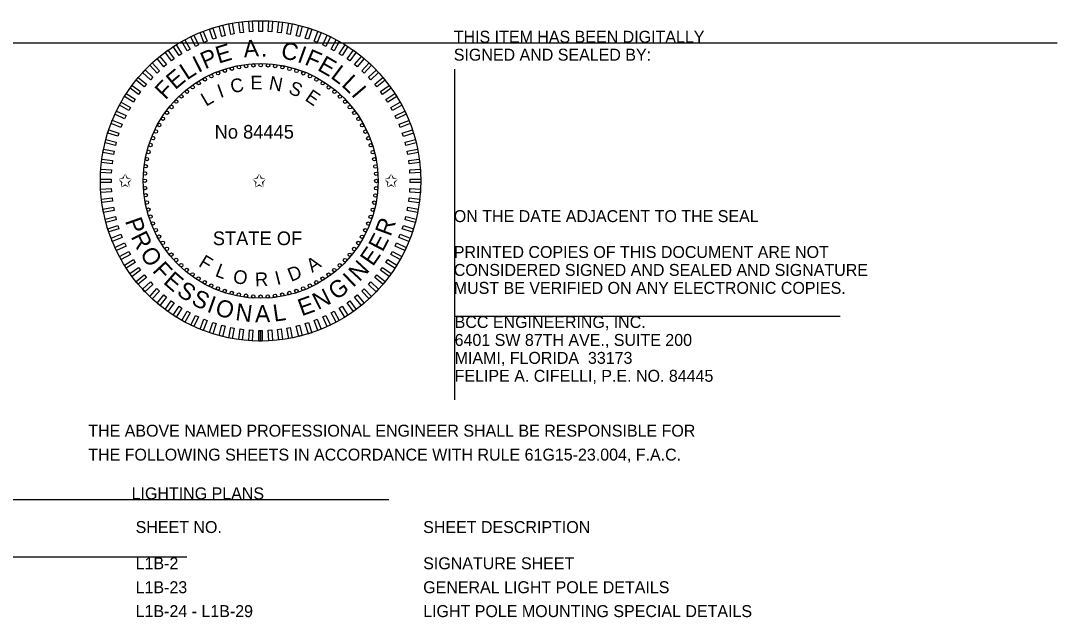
# Model space of a CAD drawing. Extents: x -811.2 to -755.6, y -2295.2 to -2235.1.
# Drawn here: x -802.94 to -796.87, y -2238.99 to -2235.5 of the extents above; entities that cross this region are included whole.
import ezdxf

# ---------------------------------------------------------------- set-up
doc = ezdxf.new("R2010")
doc.units = 0
for name, color, linetype in [('Logo_dp', 7, 'Continuous'), ('NonPlottingEle_dp', 7, 'Continuous'), ('ScratchEle_dp', 7, 'Continuous'), ('TextMisc', 7, 'Continuous'), ('TextNotes', 7, 'Continuous')]:
    doc.layers.add(name, color=color, linetype=linetype)

msp = doc.modelspace()

# ---------------------------------------------------------------- linework, layer by layer
at = {"layer": 'Logo_dp'}
for p, q in [((-801.5429, -2237.3754), (-801.5431, -2237.3129)), ((-801.5329, -2237.3754), (-801.5331, -2237.3129)), ((-801.5229, -2237.3754), (-801.5231, -2237.3129))]:
    msp.add_line(p, q, dxfattribs=at)
for points in [[(-801.6869, -2235.5764), (-801.7067, -2235.5802), (-801.7184, -2235.5189), (-801.6986, -2235.5151)], [(-801.6325, -2235.5685), (-801.6525, -2235.571), (-801.6603, -2235.5091), (-801.6403, -2235.5065)], [(-801.5777, -2235.5639), (-801.5978, -2235.5652), (-801.6018, -2235.5029), (-801.5816, -2235.5016)], [(-801.5227, -2235.5629), (-801.5429, -2235.5629), (-801.5429, -2235.5004), (-801.5227, -2235.5004)], [(-801.4678, -2235.5652), (-801.488, -2235.564), (-801.484, -2235.5016), (-801.4639, -2235.5029)], [(-801.4131, -2235.571), (-801.4332, -2235.5685), (-801.4254, -2235.5066), (-801.4053, -2235.5091)], [(-801.359, -2235.5803), (-801.3788, -2235.5765), (-801.3671, -2235.5152), (-801.3473, -2235.5189)], [(-801.8456, -2235.6206), (-801.8643, -2235.628), (-801.8873, -2235.5699), (-801.8686, -2235.5625)], [(-801.7936, -2235.6025), (-801.8128, -2235.6088), (-801.8321, -2235.5494), (-801.8129, -2235.5432)], [(-801.7407, -2235.5878), (-801.7602, -2235.5928), (-801.7758, -2235.5324), (-801.7562, -2235.5273)], [(-801.3054, -2235.5929), (-801.325, -2235.5879), (-801.3095, -2235.5274), (-801.2899, -2235.5324)], [(-801.2528, -2235.6088), (-801.272, -2235.6026), (-801.2527, -2235.5432), (-801.2335, -2235.5494)], [(-801.2013, -2235.6281), (-801.2201, -2235.6206), (-801.1971, -2235.5626), (-801.1783, -2235.57)], [(-801.9455, -2235.6662), (-801.9632, -2235.6759), (-801.9933, -2235.6212), (-801.9756, -2235.6115)], [(-801.8963, -2235.6418), (-801.9145, -2235.6504), (-801.9411, -2235.5939), (-801.9229, -2235.5853)], [(-801.1511, -2235.6505), (-801.1694, -2235.6419), (-801.1428, -2235.5854), (-801.1246, -2235.594)], [(-801.1025, -2235.676), (-801.1201, -2235.6663), (-801.0901, -2235.6116), (-801.0724, -2235.6213)], [(-802.039, -2235.724), (-802.0553, -2235.7359), (-802.092, -2235.6853), (-802.0757, -2235.6735)], [(-801.9932, -2235.6936), (-802.0102, -2235.7044), (-802.0437, -2235.6517), (-802.0266, -2235.6409)], [(-801.0555, -2235.7045), (-801.0725, -2235.6937), (-801.039, -2235.641), (-801.022, -2235.6518)], [(-801.0104, -2235.736), (-801.0267, -2235.7241), (-800.99, -2235.6736), (-800.9737, -2235.6854)], [(-802.1245, -2235.793), (-802.1392, -2235.8069), (-802.182, -2235.7613), (-802.1672, -2235.7475)], [(-802.0828, -2235.7572), (-802.0984, -2235.77), (-802.1382, -2235.7219), (-802.1226, -2235.7091)], [(-800.9673, -2235.7702), (-800.9829, -2235.7573), (-800.9431, -2235.7092), (-800.9275, -2235.722)], [(-800.9265, -2235.807), (-800.9412, -2235.7932), (-800.8985, -2235.7477), (-800.8838, -2235.7615)], [(-802.1638, -2235.8315), (-802.1776, -2235.8462), (-802.2232, -2235.8034), (-802.2093, -2235.7887)], [(-800.8881, -2235.8463), (-800.9019, -2235.8316), (-800.8564, -2235.7889), (-800.8426, -2235.8036)], [(-802.2349, -2235.9153), (-802.2467, -2235.9316), (-802.2972, -2235.8949), (-802.2854, -2235.8786)], [(-802.2007, -2235.8723), (-802.2135, -2235.8878), (-802.2616, -2235.848), (-802.2488, -2235.8325)], [(-800.8522, -2235.888), (-800.8651, -2235.8724), (-800.817, -2235.8326), (-800.8041, -2235.8482)], [(-800.819, -2235.9318), (-800.8309, -2235.9155), (-800.7804, -2235.8788), (-800.7685, -2235.8951)], [(-802.2663, -2235.9604), (-802.2771, -2235.9775), (-802.3298, -2235.944), (-802.319, -2235.927)], [(-800.7887, -2235.9776), (-800.7995, -2235.9606), (-800.7468, -2235.9271), (-800.7359, -2235.9442)], [(-802.2948, -2236.0074), (-802.3045, -2236.0251), (-802.3593, -2235.995), (-802.3495, -2235.9773)], [(-800.7612, -2236.0253), (-800.7709, -2236.0076), (-800.7162, -2235.9775), (-800.7065, -2235.9952)], [(-802.3203, -2236.0561), (-802.3289, -2236.0744), (-802.3854, -2236.0478), (-802.3768, -2236.0295)], [(-800.7368, -2236.0745), (-800.7454, -2236.0563), (-800.6889, -2236.0297), (-800.6803, -2236.048)], [(-802.3428, -2236.1063), (-802.3502, -2236.1251), (-802.4082, -2236.1021), (-802.4008, -2236.0833)], [(-800.7156, -2236.1252), (-800.723, -2236.1065), (-800.665, -2236.0835), (-800.6575, -2236.1023)], [(-802.362, -2236.1578), (-802.3682, -2236.177), (-802.4276, -2236.1577), (-802.4214, -2236.1385)], [(-800.6976, -2236.1772), (-800.7038, -2236.158), (-800.6444, -2236.1387), (-800.6382, -2236.1579)], [(-802.3779, -2236.2104), (-802.383, -2236.23), (-802.4434, -2236.2144), (-802.4384, -2236.1949)], [(-800.6829, -2236.2301), (-800.6879, -2236.2106), (-800.6274, -2236.1951), (-800.6224, -2236.2146)], [(-802.3905, -2236.2639), (-802.3943, -2236.2837), (-802.4557, -2236.272), (-802.4519, -2236.2522)], [(-800.6715, -2236.2839), (-800.6753, -2236.2641), (-800.6139, -2236.2524), (-800.6102, -2236.2722)], [(-802.3998, -2236.3181), (-802.4023, -2236.3381), (-802.4643, -2236.3303), (-802.4617, -2236.3103)], [(-800.6635, -2236.3383), (-800.666, -2236.3183), (-800.6041, -2236.3105), (-800.6016, -2236.3305)], [(-802.4056, -2236.3728), (-802.4069, -2236.3929), (-802.4692, -2236.389), (-802.4679, -2236.3689)], [(-800.659, -2236.3931), (-800.6603, -2236.373), (-800.5979, -2236.369), (-800.5967, -2236.3892)], [(-802.408, -2236.4277), (-802.408, -2236.4479), (-802.4704, -2236.4479), (-802.4704, -2236.4277)], [(-802.4069, -2236.4827), (-802.4056, -2236.5028), (-802.4679, -2236.5067), (-802.4692, -2236.4866)], [(-800.6603, -2236.503), (-800.659, -2236.4829), (-800.5967, -2236.4868), (-800.5979, -2236.5069)], [(-800.6579, -2236.4481), (-800.6579, -2236.4279), (-800.5955, -2236.4279), (-800.5955, -2236.4481)], [(-802.4023, -2236.5375), (-802.3998, -2236.5575), (-802.4618, -2236.5653), (-802.4643, -2236.5453)], [(-800.6661, -2236.5577), (-800.6635, -2236.5376), (-800.6016, -2236.5455), (-800.6041, -2236.5655)], [(-802.3944, -2236.5918), (-802.3906, -2236.6117), (-802.4519, -2236.6234), (-802.4557, -2236.6035)], [(-800.6753, -2236.6119), (-800.6715, -2236.592), (-800.6102, -2236.6037), (-800.614, -2236.6236)], [(-802.383, -2236.6456), (-802.378, -2236.6652), (-802.4385, -2236.6807), (-802.4435, -2236.6612)], [(-800.6879, -2236.6654), (-800.6829, -2236.6458), (-800.6224, -2236.6613), (-800.6274, -2236.6809)], [(-802.3683, -2236.6986), (-802.362, -2236.7178), (-802.4214, -2236.7371), (-802.4277, -2236.7179)], [(-800.7039, -2236.718), (-800.6976, -2236.6988), (-800.6382, -2236.7181), (-800.6445, -2236.7373)], [(-802.3503, -2236.7505), (-802.3428, -2236.7693), (-802.4009, -2236.7923), (-802.4083, -2236.7735)], [(-800.7231, -2236.7695), (-800.7157, -2236.7507), (-800.6576, -2236.7737), (-800.665, -2236.7925)], [(-802.329, -2236.8012), (-802.3204, -2236.8195), (-802.3769, -2236.8461), (-802.3855, -2236.8278)], [(-802.3046, -2236.8505), (-802.2949, -2236.8682), (-802.3496, -2236.8983), (-802.3593, -2236.8806)], [(-800.7455, -2236.8197), (-800.7369, -2236.8014), (-800.6804, -2236.828), (-800.689, -2236.8463)], [(-802.2772, -2236.8982), (-802.2664, -2236.9152), (-802.3191, -2236.9487), (-802.3299, -2236.9316)], [(-800.7996, -2236.9154), (-800.7888, -2236.8983), (-800.736, -2236.9318), (-800.7469, -2236.9488)], [(-800.771, -2236.8684), (-800.7613, -2236.8507), (-800.7066, -2236.8808), (-800.7163, -2236.8984)], [(-802.2468, -2236.944), (-802.235, -2236.9603), (-802.2855, -2236.997), (-802.2973, -2236.9807)], [(-800.831, -2236.9605), (-800.8191, -2236.9441), (-800.7686, -2236.9808), (-800.7805, -2236.9972)], [(-802.2136, -2236.9878), (-802.2008, -2237.0034), (-802.2489, -2237.0432), (-802.2618, -2237.0276)], [(-802.1778, -2237.0295), (-802.1639, -2237.0442), (-802.2095, -2237.0869), (-802.2233, -2237.0722)], [(-800.902, -2237.0443), (-800.8882, -2237.0296), (-800.8427, -2237.0723), (-800.8565, -2237.0871)], [(-800.8652, -2237.0035), (-800.8523, -2236.9879), (-800.8042, -2237.0278), (-800.8171, -2237.0433)], [(-802.1394, -2237.0688), (-802.1246, -2237.0826), (-802.1674, -2237.1281), (-802.1821, -2237.1143)], [(-800.9414, -2237.0827), (-800.9266, -2237.0689), (-800.8839, -2237.1144), (-800.8986, -2237.1282)], [(-802.0985, -2237.1056), (-802.083, -2237.1185), (-802.1228, -2237.1666), (-802.1383, -2237.1537)], [(-802.0555, -2237.1398), (-802.0392, -2237.1517), (-802.0759, -2237.2022), (-802.0922, -2237.1903)], [(-801.0268, -2237.1518), (-801.0105, -2237.1399), (-800.9738, -2237.1904), (-800.9901, -2237.2023)], [(-800.983, -2237.1186), (-800.9675, -2237.1057), (-800.9277, -2237.1538), (-800.9432, -2237.1667)], [(-802.0104, -2237.1712), (-801.9933, -2237.1821), (-802.0268, -2237.2348), (-802.0438, -2237.224)], [(-801.9634, -2237.1998), (-801.9457, -2237.2095), (-801.9758, -2237.2642), (-801.9935, -2237.2545)], [(-801.1203, -2237.2096), (-801.1026, -2237.1999), (-801.0725, -2237.2546), (-801.0902, -2237.2643)], [(-801.0727, -2237.1822), (-801.0556, -2237.1713), (-801.0222, -2237.2241), (-801.0392, -2237.2349)], [(-801.9147, -2237.2253), (-801.8964, -2237.2339), (-801.923, -2237.2904), (-801.9413, -2237.2818)], [(-801.8645, -2237.2477), (-801.8457, -2237.2552), (-801.8687, -2237.3132), (-801.8875, -2237.3058)], [(-801.813, -2237.2669), (-801.7938, -2237.2732), (-801.8131, -2237.3326), (-801.8323, -2237.3263)], [(-801.2722, -2237.2732), (-801.253, -2237.267), (-801.2337, -2237.3264), (-801.2529, -2237.3326)], [(-801.2203, -2237.2552), (-801.2015, -2237.2478), (-801.1785, -2237.3058), (-801.1973, -2237.3133)], [(-801.1696, -2237.234), (-801.1513, -2237.2254), (-801.1247, -2237.2819), (-801.143, -2237.2905)], [(-801.7604, -2237.2829), (-801.7409, -2237.2879), (-801.7564, -2237.3484), (-801.7759, -2237.3434)], [(-801.7069, -2237.2955), (-801.6871, -2237.2993), (-801.6988, -2237.3606), (-801.7186, -2237.3568)], [(-801.6527, -2237.3047), (-801.6327, -2237.3073), (-801.6405, -2237.3692), (-801.6605, -2237.3667)], [(-801.598, -2237.3106), (-801.5779, -2237.3118), (-801.5818, -2237.3741), (-801.602, -2237.3729)], [(-801.5431, -2237.3129), (-801.5229, -2237.3129), (-801.5229, -2237.3754), (-801.5431, -2237.3754)], [(-801.4881, -2237.3118), (-801.468, -2237.3106), (-801.4641, -2237.3729), (-801.4842, -2237.3741)], [(-801.4334, -2237.3073), (-801.4133, -2237.3048), (-801.4055, -2237.3667), (-801.4255, -2237.3692)], [(-801.379, -2237.2993), (-801.3591, -2237.2955), (-801.3474, -2237.3569), (-801.3673, -2237.3607)], [(-801.3252, -2237.288), (-801.3056, -2237.2829), (-801.2901, -2237.3434), (-801.3097, -2237.3484)]]:
    msp.add_lwpolyline(points, close=True, dxfattribs=at)
for centre in [(-801.6173, -2235.7657), (-801.5749, -2235.7617), (-801.5324, -2235.7604), (-801.4898, -2235.7618), (-801.4475, -2235.7658), (-801.8209, -2235.8247), (-801.7818, -2235.8078), (-801.7417, -2235.7934), (-801.7009, -2235.7816), (-801.6593, -2235.7723), (-801.4054, -2235.7725), (-801.3639, -2235.7818), (-801.323, -2235.7938), (-801.283, -2235.8082), (-801.244, -2235.8251), (-801.9307, -2235.8895), (-801.8955, -2235.8656), (-801.8588, -2235.8439), (-801.2061, -2235.8445), (-801.1694, -2235.8662), (-801.9963, -2235.9436), (-801.9643, -2235.9155), (-801.1343, -2235.8901), (-801.1007, -2235.9163), (-801.0688, -2235.9444), (-802.0546, -2236.0056), (-802.0264, -2235.9737), (-801.0387, -2235.9745), (-801.0106, -2236.0065), (-802.0807, -2236.0392), (-800.9845, -2236.0401), (-802.1263, -2236.111), (-802.1046, -2236.0744), (-800.9606, -2236.0754), (-800.939, -2236.112), (-802.1626, -2236.188), (-802.1457, -2236.1489), (-800.9197, -2236.1499), (-800.9028, -2236.189), (-802.1771, -2236.228), (-800.8884, -2236.2291), (-802.1983, -2236.3104), (-802.189, -2236.2689), (-800.8766, -2236.27), (-800.8674, -2236.3115), (-802.205, -2236.3524), (-800.8607, -2236.3535), (-802.209, -2236.3948), (-800.8568, -2236.3959), (-802.2104, -2236.4373), (-802.2091, -2236.4799), (-800.8568, -2236.481), (-800.8555, -2236.4385), (-802.2051, -2236.5222), (-800.8609, -2236.5234), (-802.1985, -2236.5643), (-802.1893, -2236.6058), (-800.8769, -2236.6069), (-800.8676, -2236.5654), (-802.1774, -2236.6467), (-800.8888, -2236.6478), (-802.163, -2236.6868), (-802.1462, -2236.7258), (-800.9202, -2236.7269), (-800.9032, -2236.6878), (-802.1269, -2236.7638), (-800.9395, -2236.7648), (-802.1052, -2236.8004), (-802.0813, -2236.8356), (-800.9852, -2236.8366), (-800.9612, -2236.8014), (-802.0553, -2236.8693), (-802.0272, -2236.9012), (-801.0395, -2236.9021), (-801.0113, -2236.8702), (-801.9971, -2236.9314), (-801.9652, -2236.9595), (-801.1015, -2236.9602), (-801.0696, -2236.9321), (-801.9316, -2236.9856), (-801.8964, -2237.0096), (-801.8598, -2237.0313), (-801.207, -2237.0318), (-801.1704, -2237.0102), (-801.1352, -2236.9863), (-801.8219, -2237.0506), (-801.7828, -2237.0676), (-801.7428, -2237.082), (-801.702, -2237.0939), (-801.365, -2237.0942), (-801.3241, -2237.0824), (-801.2841, -2237.068), (-801.245, -2237.0511), (-801.6604, -2237.1033), (-801.6184, -2237.1099), (-801.576, -2237.114), (-801.5329, -2237.1154), (-801.4909, -2237.1141), (-801.4486, -2237.1101), (-801.4065, -2237.1035)]:
    msp.add_circle(centre, 0.01, dxfattribs=at)
at = {"layer": 'NonPlottingEle_dp'}
for radius in [0.9375, 0.6875]:
    msp.add_circle((-801.5329, -2236.4379), radius, dxfattribs=at)
at = {"layer": 'ScratchEle_dp'}
for p, q in [((-808.3596, -2235.6292), (-796.8708, -2235.6292)), ((-800.3974, -2235.7843), (-800.3974, -2237.719)), ((-800.3974, -2237.229), (-798.1407, -2237.229)), ((-809.3854, -2238.3022), (-800.7818, -2238.3022)), ((-801.9648, -2238.6414), (-810.4432, -2238.6414))]:
    msp.add_line(p, q, dxfattribs=at)

# ---------------------------------------------------------------- texts
at = {"layer": 'Logo_dp'}
for s, height, rotation, p in [('E', 0.1, 16.54261, (-801.7793, -2235.7522)), ('A', 0.1, 4.42103, (-801.6298, -2235.7157)), ('C', 0.1, 347.7999, (-801.4192, -2235.7182)), ('P', 0.1, 23.28287, (-801.8581, -2235.7858)), ('.', 0.1, 356.65403, (-801.5313, -2235.7092)), ('I', 0.1, 340.0631, (-801.3234, -2235.74)), ('F', 0.1, 336.52991, (-801.2807, -2235.7543)), ('L', 0.1, 33.07918, (-801.9643, -2235.8507)), ('I', 0.1, 26.81606, (-801.8977, -2235.8071)), ('E', 0.1, 330.07956, (-801.2055, -2235.7869)), ('L', 0.1, 323.03732, (-801.1282, -2235.832)), ('E', 0.1, 40.12142, (-802.033, -2235.908)), ('L', 0.1, 316.7742, (-801.0645, -2235.8797)), ('F', 0.1, 46.57177, (-802.0894, -2235.9675)), ('I', 0.08, 20.01168, (-801.7686, -2235.9538)), ('C', 0.08, 12.20255, (-801.7007, -2235.9263)), ('E', 0.08, 0.41861, (-801.5926, -2235.9028)), ('N', 0.08, 349.29143, (-801.4883, -2235.9013)), ('S', 0.08, 337.02207, (-801.3753, -2235.9231)), ('I', 0.1, 310.51108, (-801.0064, -2235.9342)), ('L', 0.08, 30.40215, (-801.8521, -2236.0043)), ('E', 0.08, 325.86633, (-801.2786, -2235.9633)), ('P', 0.1, 289.40551, (-802.3276, -2236.6725)), ('R', 0.1, 69.5134, (-800.7727, -2236.7676)), ('R', 0.1, 296.14576, (-802.2946, -2236.7641)), ('E', 0.1, 62.47116, (-800.8189, -2236.8583)), ('O', 0.1, 303.96711, (-802.2431, -2236.8647)), ('E', 0.1, 55.42892, (-800.8758, -2236.9427)), ('F', 0.1, 312.62798, (-802.1708, -2236.9668)), ('F', 0.08, 328.72408, (-801.901, -2236.9345)), ('A', 0.08, 34.49917, (-801.2311, -2236.9773)), ('N', 0.1, 47.17876, (-800.9551, -2237.0317)), ('E', 0.1, 319.07833, (-802.1073, -2237.0351)), ('L', 0.08, 339.29159, (-801.8037, -2236.9936)), ('O', 0.08, 349.68206, (-801.699, -2237.0333)), ('I', 0.08, 14.20366, (-801.4369, -2237.0485)), ('D', 0.08, 22.01279, (-801.3549, -2237.0298)), ('R', 0.08, 2.33977, (-801.5645, -2237.0552)), ('G', 0.1, 35.11153, (-801.092, -2237.1394)), ('I', 0.1, 43.64556, (-800.9928, -2237.0662)), ('S', 0.1, 326.12056, (-802.0297, -2237.101)), ('S', 0.1, 333.193, (-801.9443, -2237.1572)), ('N', 0.1, 26.86136, (-801.1972, -2237.1954)), ('I', 0.1, 340.26543, (-801.8526, -2237.2023)), ('O', 0.1, 343.79863, (-801.8049, -2237.2206)), ('E', 0.1, 19.81912, (-801.2926, -2237.2309)), ('N', 0.1, 352.45949, (-801.6839, -2237.2526)), ('A', 0.1, 0.70966, (-801.5655, -2237.2659)), ('L', 0.1, 8.47665, (-801.4533, -2237.2627))]:
    msp.add_text(s, height=height, rotation=rotation, dxfattribs=at).set_placement(p)
for s, p in [('No 84445', (-801.8019, -2236.1907)), ('✩', (-802.3679, -2236.4758)), ('✩', (-801.5832, -2236.4758)), ('✩', (-800.8113, -2236.4758)), ('STATE OF', (-801.8126, -2236.8141))]:
    msp.add_text(s, height=0.08, dxfattribs=at).set_placement(p)
at = {"layer": 'TextMisc'}
for s, p in [('THIS ITEM HAS BEEN DIGITALLY', (-800.4024, -2235.6292)), ('SIGNED AND SEALED BY:', (-800.4024, -2235.7342)), ('ON THE DATE ADJACENT TO THE SEAL', (-800.4024, -2236.6792)), ('PRINTED COPIES OF THIS DOCUMENT ARE NOT ', (-800.4024, -2236.8892)), ('CONSIDERED SIGNED AND SEALED AND SIGNATURE ', (-800.4024, -2236.9942)), ('MUST BE VERIFIED ON ANY ELECTRONIC COPIES.', (-800.4024, -2237.0992)), ('BCC ENGINEERING, INC.', (-800.3974, -2237.299)), ('6401 SW 87TH AVE., SUITE 200', (-800.3974, -2237.404)), ('MIAMI, FLORIDA  33173', (-800.3974, -2237.509)), ('FELIPE A. CIFELLI, P.E. NO. 84445', (-800.3974, -2237.614)), ('THE ABOVE NAMED PROFESSIONAL ENGINEER SHALL BE RESPONSIBLE FOR ', (-802.5415, -2237.9352)), ('THE FOLLOWING SHEETS IN ACCORDANCE WITH RULE 61G15-23.004, F.A.C.', (-802.5415, -2238.0752)), ('LIGHTING PLANS', (-802.2878, -2238.3022))]:
    msp.add_text(s, height=0.07, dxfattribs=at).set_placement(p)
at = {"layer": 'TextNotes'}
for s, p in [('SHEET NO.', (-802.2643, -2238.4992)), ('SHEET DESCRIPTION', (-800.5815, -2238.4992)), ('L1B-2', (-802.2643, -2238.7114)), ('SIGNATURE SHEET', (-800.5815, -2238.7114)), ('L1B-23', (-802.2643, -2238.8514)), ('GENERAL LIGHT POLE DETAILS', (-800.5815, -2238.8514)), ('L1B-24 - L1B-29', (-802.2643, -2238.9914)), ('LIGHT POLE MOUNTING SPECIAL DETAILS', (-800.5815, -2238.9914))]:
    msp.add_text(s, height=0.07, dxfattribs=at).set_placement(p)

doc.saveas('drawing.dxf')
